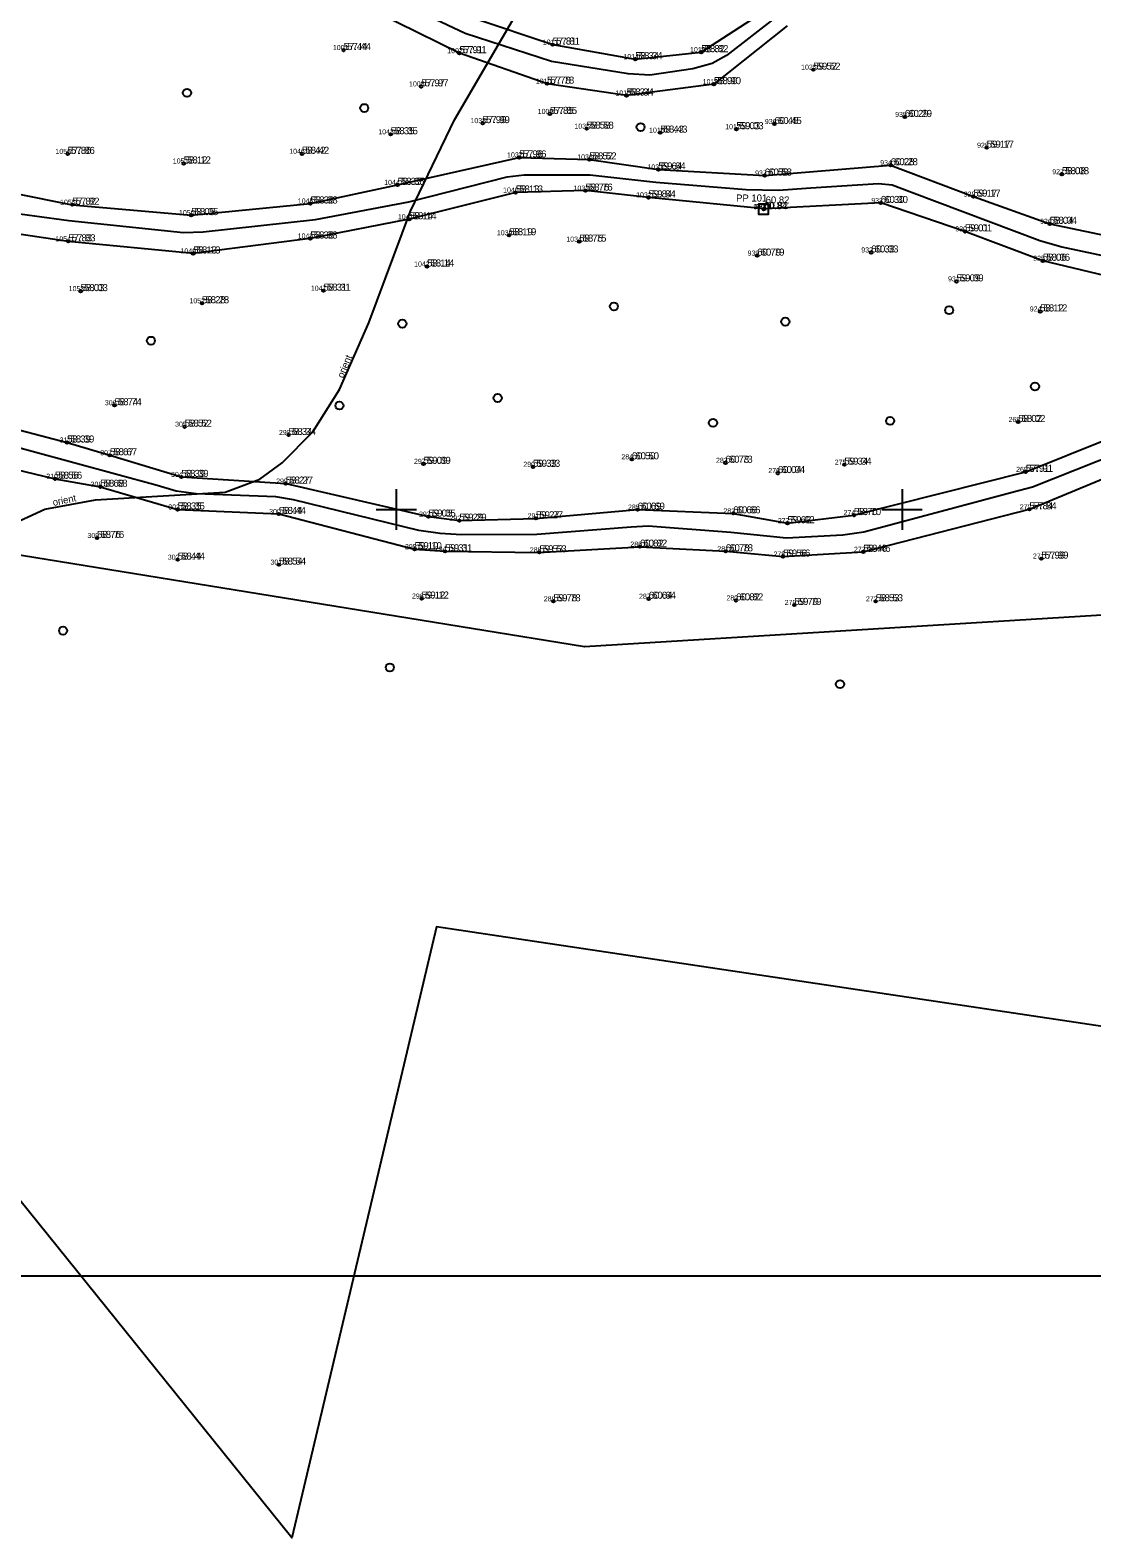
# Model space of a CAD drawing. Extents: x 554846 to 556995, y 6445875 to 6446723.
# Drawn here: x 555263.8 to 555368.8, y 6445948.4 to 6446097.4 of the extents above; entities that cross this region are included whole.
import ezdxf

# ---------------------------------------------------------------- set-up
doc = ezdxf.new("R2010")
doc.units = 0
for name, color, linetype in [('ALUSVORK', 7, 'Continuous'), ('HALJASTUS', 7, 'Continuous'), ('KORGUS-EH2000', 7, 'Continuous'), ('MOOTKORG-EH2000', 7, 'Continuous'), ('MOOTKORGMUU-EH2000', 7, 'Continuous'), ('MOOTMPUNKT', 7, 'Continuous'), ('MOOTNR', 7, 'Continuous'), ('MOOTPIIR', 7, 'Continuous'), ('PIIR', 7, 'Continuous'), ('SITRASS', 7, 'Continuous'), ('TEE', 7, 'Continuous'), ('VORK', 7, 'Continuous'), ('VORMISTUS', 7, 'Continuous')]:
    doc.layers.add(name, color=color, linetype=linetype)

msp = doc.modelspace()

# ---------------------------------------------------------------- linework, layer by layer
at = {"layer": 'ALUSVORK'}
msp.add_lwpolyline([(555336.81, 6446080.17), (555335.81, 6446080.17), (555335.81, 6446079.17), (555336.81, 6446079.17)], close=True, dxfattribs=at)
msp.add_circle((555336.31, 6446079.67), 0.05, dxfattribs=at)
at = {"layer": 'HALJASTUS'}
for centre in [(555279.31, 6446091.18), (555296.83, 6446089.67), (555324.15, 6446087.79), (555321.51, 6446070.07), (555354.66, 6446069.69), (555300.6, 6446068.37), (555338.46, 6446068.56), (555275.74, 6446066.68), (555363.14, 6446062.15), (555310.02, 6446061.02), (555294.38, 6446060.27), (555331.31, 6446058.57), (555348.82, 6446058.76), (555267.06, 6446038.03), (555299.36, 6446034.4), (555343.87, 6446032.75)]:
    msp.add_circle(centre, 0.4, dxfattribs=at)
at = {"layer": 'KORGUS-EH2000'}
for centre in [(555294.8, 6446095.4), (555315.46, 6446095.94), (555330.14, 6446095.19), (555306.24, 6446095.09), (555323.63, 6446094.5), (555341.22, 6446093.46), (555302.46, 6446091.81), (555314.9, 6446092.08), (555322.76, 6446090.91), (555331.39, 6446092.03), (555308.53, 6446088.18), (555315.18, 6446089.09), (555337.39, 6446088.09), (555350.27, 6446088.79), (555299.44, 6446087.08), (555318.81, 6446087.63), (555326.09, 6446087.24), (555333.62, 6446087.58), (555267.5, 6446085.14), (555290.67, 6446085.15), (555312.15, 6446084.79), (555358.37, 6446085.75), (555278.98, 6446084.19), (555319.08, 6446084.59), (555325.91, 6446083.6), (555348.87, 6446084.02), (555300.12, 6446082.08), (555336.42, 6446083), (555365.8, 6446083.13), (555291.51, 6446080.24), (555311.81, 6446081.32), (555318.7, 6446081.51), (555324.93, 6446080.84), (555347.89, 6446080.29), (555357.05, 6446080.92), (555267.96, 6446080.12), (555279.72, 6446079.09), (555301.28, 6446078.68), (555356.22, 6446077.48), (555364.6, 6446078.23), (555267.57, 6446076.5), (555291.5, 6446076.78), (555311.15, 6446077.1), (555318.08, 6446076.47), (555279.92, 6446075.3), (555335.68, 6446075.09), (555346.95, 6446075.4), (555363.92, 6446074.58), (555303.04, 6446074.01), (555268.79, 6446071.58), (555292.8, 6446071.62), (555355.38, 6446072.54), (555280.78, 6446070.38), (555363.65, 6446069.57), (555272.14, 6446060.3), (555279.08, 6446058.18), (555361.48, 6446058.65), (555267.45, 6446056.62), (555289.35, 6446057.36), (555271.68, 6446055.36), (555323.28, 6446054.96), (555302.69, 6446054.51), (555313.51, 6446054.22), (555332.54, 6446054.62), (555337.72, 6446053.6), (555344.3, 6446054.43), (555362.23, 6446053.72), (555266.25, 6446053.04), (555270.73, 6446052.25), (555278.75, 6446053.22), (555289.07, 6446052.56), (555278.38, 6446050), (555288.38, 6446049.56), (555303.18, 6446049.3), (555313.8, 6446049.13), (555323.86, 6446049.99), (555333.31, 6446049.62), (555345.24, 6446049.45), (555362.59, 6446050.02), (555306.24, 6446048.9), (555338.67, 6446048.65), (555270.41, 6446047.19), (555301.81, 6446046.08), (555324.09, 6446046.33), (555278.39, 6446045.04), (555288.39, 6446044.55), (555304.82, 6446045.87), (555314.15, 6446045.77), (555332.57, 6446045.87), (555338.24, 6446045.35), (555346.17, 6446045.82), (555363.77, 6446045.15), (555302.5, 6446041.2), (555315.53, 6446040.93), (555324.95, 6446041.18), (555333.59, 6446041.02), (555339.35, 6446040.57), (555347.4, 6446040.93)]:
    msp.add_circle(centre, 0.125, dxfattribs=at)
at = {"layer": 'MOOTMPUNKT'}
for centre in [(555294.8, 6446095.4), (555315.46, 6446095.94), (555330.14, 6446095.19), (555306.24, 6446095.09), (555323.63, 6446094.5), (555341.22, 6446093.46), (555302.46, 6446091.81), (555314.9, 6446092.08), (555322.76, 6446090.91), (555331.39, 6446092.03), (555308.53, 6446088.18), (555315.18, 6446089.09), (555337.39, 6446088.09), (555350.27, 6446088.79), (555299.44, 6446087.08), (555318.81, 6446087.63), (555326.09, 6446087.24), (555333.62, 6446087.58), (555267.5, 6446085.14), (555290.67, 6446085.15), (555312.15, 6446084.79), (555358.37, 6446085.75), (555278.98, 6446084.19), (555319.08, 6446084.59), (555325.91, 6446083.6), (555348.87, 6446084.02), (555300.12, 6446082.08), (555336.42, 6446083), (555365.8, 6446083.13), (555291.51, 6446080.24), (555311.81, 6446081.32), (555318.7, 6446081.51), (555324.93, 6446080.84), (555347.89, 6446080.29), (555357.05, 6446080.92), (555267.96, 6446080.12), (555279.72, 6446079.09), (555336.31, 6446079.67), (555336.39, 6446079.7), (555301.28, 6446078.68), (555356.22, 6446077.48), (555364.6, 6446078.23), (555267.57, 6446076.5), (555291.5, 6446076.78), (555311.15, 6446077.1), (555318.08, 6446076.47), (555279.92, 6446075.3), (555335.68, 6446075.09), (555346.95, 6446075.4), (555363.92, 6446074.58), (555303.04, 6446074.01), (555268.79, 6446071.58), (555292.8, 6446071.62), (555355.38, 6446072.54), (555280.78, 6446070.38), (555363.65, 6446069.57), (555272.14, 6446060.3), (555279.08, 6446058.18), (555361.48, 6446058.65), (555267.45, 6446056.62), (555289.35, 6446057.36), (555271.68, 6446055.36), (555323.28, 6446054.96), (555302.69, 6446054.51), (555313.51, 6446054.22), (555332.54, 6446054.62), (555337.72, 6446053.6), (555344.3, 6446054.43), (555362.23, 6446053.72), (555266.25, 6446053.04), (555270.73, 6446052.25), (555278.75, 6446053.22), (555289.07, 6446052.56), (555278.38, 6446050), (555288.38, 6446049.56), (555303.18, 6446049.3), (555313.8, 6446049.13), (555323.86, 6446049.99), (555333.31, 6446049.62), (555345.24, 6446049.45), (555362.59, 6446050.02), (555306.24, 6446048.9), (555338.67, 6446048.65), (555270.41, 6446047.19), (555301.81, 6446046.08), (555324.09, 6446046.33), (555278.39, 6446045.04), (555288.39, 6446044.55), (555304.82, 6446045.87), (555314.15, 6446045.77), (555332.57, 6446045.87), (555338.24, 6446045.35), (555346.17, 6446045.82), (555363.77, 6446045.15), (555302.5, 6446041.2), (555315.53, 6446040.93), (555324.95, 6446041.18), (555333.59, 6446041.02), (555339.35, 6446040.57), (555347.4, 6446040.93)]:
    msp.add_circle(centre, 0.125, dxfattribs=at)
at = {"layer": 'MOOTPIIR'}
msp.add_lwpolyline([(555856.56, 6446356.05), (555752.84, 6446263.06), (555653.54, 6446239.26), (555594.53, 6446196.06), (555554.98, 6446185.17), (555476.19, 6446171.98), (555473.22, 6446121.18), (555464.98, 6446086.88), (555439.93, 6446060.82), (555399.38, 6446041.36), (555318.62, 6446036.42), (555233.24, 6446050.27)], dxfattribs=at)
at = {"layer": 'PIIR'}
msp.add_lwpolyline([(555848.15, 6446270.05), (555770.44, 6446257.1), (555601.76, 6446236.19), (555592.08, 6446205.8), (555590.17, 6446199.81), (555547.72, 6446198.88), (555471.93, 6446166.68), (555437.75, 6445988.89), (555430.84, 6445989.84), (555424.9, 6445990.66), (555394.94, 6445995.15), (555348.46, 6446002.11), (555303.97, 6446008.78), (555290.27, 6445950.91), (555289.66, 6445948.39), (555259.76, 6445985.47)], dxfattribs=at)
at = {"layer": 'SITRASS'}
msp.add_lwpolyline([(555261.53, 6446048.32), (555265.26, 6446050.03), (555270.26, 6446050.97), (555283.07, 6446051.71), (555286.51, 6446053), (555288.72, 6446054.6), (555291.74, 6446057.68), (555294.38, 6446061.86), (555297.27, 6446068.45), (555301.4, 6446079.47), (555305.76, 6446088.51), (555311.73, 6446098.73)], dxfattribs=at)
at = {"layer": 'TEE'}
for points in [[(555256.61, 6446082.39), (555267.96, 6446080.12), (555279.72, 6446079.09), (555291.51, 6446080.24), (555300.12, 6446082.08), (555312.15, 6446084.79), (555319.08, 6446084.59), (555325.91, 6446083.6), (555336.42, 6446083), (555348.87, 6446084.02), (555357.05, 6446080.92), (555364.6, 6446078.23), (555374.38, 6446076.19), (555383.78, 6446075.37), (555390.8, 6446076.13), (555396.02, 6446079.96), (555405.42, 6446089.57), (555411.89, 6446096.58), (555419.56, 6446103.46)], [(555419.45, 6446099.97), (555414.31, 6446095.01), (555407.49, 6446086.81), (555398.56, 6446078), (555391.3, 6446072.86), (555383.86, 6446071.46), (555373.85, 6446072.2), (555363.92, 6446074.58), (555356.22, 6446077.48), (555347.89, 6446080.29), (555336.39, 6446079.7), (555324.93, 6446080.84), (555318.7, 6446081.51), (555311.81, 6446081.32), (555301.28, 6446078.68), (555291.5, 6446076.78), (555279.92, 6446075.3), (555267.57, 6446076.5), (555255.14, 6446078.33)], [(555337.65, 6446098.75), (555332.63, 6446094.86), (555331.22, 6446094.06), (555329.3, 6446093.54), (555325.06, 6446092.92), (555322.93, 6446093.04), (555315.35, 6446094.28), (555306.81, 6446097.03), (555299.18, 6446100.65)], [(555338.65, 6446097.8), (555331.39, 6446092.03), (555322.76, 6446090.91), (555314.9, 6446092.08), (555306.24, 6446095.09), (555298.02, 6446099.16)], [(555307.6, 6446098.59), (555315.46, 6446095.94), (555323.63, 6446094.5), (555330.14, 6446095.19), (555336.09, 6446099.06)], [(555260.14, 6446058.52), (555267.45, 6446056.62), (555271.68, 6446055.36), (555278.75, 6446053.22), (555289.07, 6446052.56), (555303.18, 6446049.3), (555306.24, 6446048.9), (555313.8, 6446049.13), (555323.86, 6446049.99), (555333.31, 6446049.62), (555338.67, 6446048.65), (555345.24, 6446049.45), (555362.23, 6446053.72), (555370.46, 6446057.03), (555379.96, 6446060.43), (555389.86, 6446059.75), (555402.8, 6446059.54), (555410.15, 6446060.85), (555416.44, 6446065.08), (555425.62, 6446070.28), (555431.48, 6446073.77), (555442.06, 6446083.57), (555449.19, 6446092.47), (555452.21, 6446097.57)], [(555260.83, 6446079.49), (555267.63, 6446078.55), (555278.96, 6446077.39), (555280.91, 6446077.45), (555292.02, 6446078.67), (555301.24, 6446080.41), (555310.97, 6446082.87), (555312.63, 6446083.06), (555315.59, 6446083.06), (555319.13, 6446083.06), (555325.66, 6446082.35), (555334.6, 6446081.62), (555337.8, 6446081.56), (555340.99, 6446081.78), (555345.59, 6446082.09), (555347.68, 6446082.23), (555349.03, 6446082.09), (555350.95, 6446081.36), (555363.63, 6446076.59), (555365.8, 6446075.96), (555374.01, 6446074.2)], [(555371.37, 6446055.57), (555362.89, 6446052.22), (555360.89, 6446051.68), (555346.21, 6446047.75), (555344.13, 6446047.47), (555338.59, 6446047.16), (555333.07, 6446047.72), (555324.91, 6446048.34), (555323.23, 6446048.27), (555313.89, 6446047.54), (555306.46, 6446047.5), (555304.33, 6446047.64), (555302.22, 6446047.92), (555289.82, 6446050.95), (555288.08, 6446051.24), (555280.21, 6446051.55), (555278.25, 6446051.8), (555276.36, 6446052.39), (555259.85, 6446056.85)], [(555259.12, 6446054.74), (555266.25, 6446053.04), (555270.73, 6446052.25), (555278.38, 6446050), (555288.38, 6446049.56), (555301.81, 6446046.08), (555304.82, 6446045.87), (555314.03, 6446045.77), (555324.09, 6446046.33), (555332.57, 6446045.87), (555338.24, 6446045.35), (555346.17, 6446045.82), (555362.59, 6446050.02), (555371.83, 6446053.87)]]:
    msp.add_lwpolyline(points, dxfattribs=at)
at = {"layer": 'VORK'}
for p, q in [((555300, 6446052), (555300, 6446048)), ((555350, 6446052), (555350, 6446048)), ((555298, 6446050), (555302, 6446050)), ((555348, 6446050), (555352, 6446050))]:
    msp.add_line(p, q, dxfattribs=at)
at = {"layer": 'VORMISTUS'}
msp.add_lwpolyline([(555573.73, 6445974.27), (555573.73, 6446387.77), (554994.23, 6446387.77), (554994.23, 6445974.27), (555573.73, 6445974.27)], dxfattribs=at)

# ---------------------------------------------------------------- texts
at = {"layer": 'ALUSVORK'}
for s, p in [('PP 101', (555333.6, 6446080.43)), ('60.82', (555336.52, 6446080.24))]:
    msp.add_text(s, height=0.7, dxfattribs=at).set_placement(p)
at = {"layer": 'KORGUS-EH2000'}
for s, p in [('57.44', (555295.15, 6446095.4)), ('57.91', (555306.59, 6446095.09)), ('57.81', (555315.81, 6446095.94)), ('58.82', (555330.49, 6446095.19)), ('58.34', (555323.98, 6446094.5)), ('59.52', (555341.57, 6446093.46)), ('57.97', (555302.81, 6446091.81)), ('57.78', (555315.25, 6446092.08)), ('58.90', (555331.74, 6446092.03)), ('58.34', (555323.11, 6446090.91)), ('57.85', (555315.53, 6446089.09)), ('60.29', (555350.62, 6446088.79)), ('57.99', (555308.88, 6446088.18)), ('58.58', (555319.16, 6446087.63)), ('58.43', (555326.44, 6446087.24)), ('59.03', (555333.97, 6446087.58)), ('60.45', (555337.74, 6446088.09)), ('58.35', (555299.79, 6446087.08)), ('59.17', (555358.72, 6446085.75)), ('57.86', (555267.85, 6446085.14)), ('58.12', (555279.33, 6446084.19)), ('58.42', (555291.02, 6446085.15)), ('57.96', (555312.5, 6446084.79)), ('58.52', (555319.43, 6446084.59)), ('59.64', (555326.26, 6446083.6)), ('60.58', (555336.77, 6446083)), ('60.28', (555349.22, 6446084.02)), ('58.08', (555366.15, 6446083.13)), ('58.35', (555300.47, 6446082.08)), ('58.13', (555312.16, 6446081.32)), ('58.76', (555319.05, 6446081.51)), ('57.82', (555268.31, 6446080.12)), ('58.38', (555291.86, 6446080.24)), ('59.84', (555325.28, 6446080.84)), ('60.30', (555348.24, 6446080.29)), ('59.17', (555357.4, 6446080.92)), ('58.05', (555280.07, 6446079.09)), ('58.14', (555301.63, 6446078.68)), ('58.04', (555364.95, 6446078.23)), ('58.38', (555291.85, 6446076.78)), ('58.19', (555311.5, 6446077.1)), ('59.01', (555356.57, 6446077.48)), ('57.83', (555267.92, 6446076.5)), ('58.13', (555280.27, 6446075.3)), ('58.75', (555318.43, 6446076.47)), ('60.33', (555347.3, 6446075.4)), ('58.14', (555303.39, 6446074.01)), ('60.79', (555336.03, 6446075.09)), ('58.06', (555364.27, 6446074.58)), ('59.09', (555355.72, 6446072.54)), ('58.03', (555269.14, 6446071.58)), ('58.31', (555293.15, 6446071.62)), ('58.28', (555281.13, 6446070.38)), ('58.12', (555364, 6446069.57)), ('58.74', (555272.49, 6446060.3)), ('58.52', (555279.43, 6446058.18)), ('58.34', (555289.7, 6446057.36)), ('58.02', (555361.83, 6446058.65)), ('58.39', (555267.8, 6446056.62)), ('58.67', (555272.03, 6446055.36)), ('59.09', (555303.04, 6446054.51)), ('60.50', (555323.63, 6446054.96)), ('60.73', (555332.89, 6446054.62)), ('59.34', (555344.65, 6446054.43)), ('58.56', (555266.6, 6446053.04)), ('58.39', (555279.1, 6446053.22)), ('59.33', (555313.86, 6446054.22)), ('60.04', (555338.07, 6446053.6)), ('57.91', (555362.58, 6446053.72)), ('58.68', (555271.08, 6446052.25)), ('58.27', (555289.42, 6446052.56)), ('58.35', (555278.73, 6446050)), ('60.69', (555324.21, 6446049.99)), ('57.84', (555362.94, 6446050.02)), ('58.44', (555288.73, 6446049.56)), ('59.05', (555303.53, 6446049.3)), ('59.29', (555306.59, 6446048.9)), ('59.27', (555314.15, 6446049.13)), ('60.66', (555333.66, 6446049.62)), ('59.62', (555339.02, 6446048.65)), ('58.70', (555345.59, 6446049.45)), ('58.76', (555270.76, 6446047.19)), ('59.10', (555302.16, 6446046.08)), ('59.31', (555305.17, 6446045.87)), ('59.53', (555314.5, 6446045.77)), ('60.82', (555324.44, 6446046.33)), ('60.78', (555332.92, 6446045.87)), ('58.46', (555346.52, 6446045.82)), ('58.44', (555278.74, 6446045.04)), ('58.54', (555288.74, 6446044.55)), ('59.56', (555338.59, 6446045.35)), ('57.99', (555364.11, 6446045.15)), ('59.12', (555302.85, 6446041.2)), ('59.78', (555315.88, 6446040.93)), ('60.64', (555325.3, 6446041.18)), ('60.82', (555333.94, 6446041.02)), ('58.53', (555347.75, 6446040.93)), ('59.79', (555339.7, 6446040.57))]:
    msp.add_text(s, height=0.7, dxfattribs=at).set_placement(p)
at = {"layer": 'MOOTKORG-EH2000'}
for s, p in [('57.44', (555294.8, 6446095.4)), ('57.91', (555306.24, 6446095.09)), ('57.81', (555315.46, 6446095.94)), ('58.82', (555330.14, 6446095.19)), ('58.34', (555323.63, 6446094.5)), ('59.52', (555341.22, 6446093.46)), ('57.97', (555302.46, 6446091.81)), ('57.78', (555314.9, 6446092.08)), ('58.90', (555331.39, 6446092.03)), ('58.34', (555322.76, 6446090.91)), ('57.85', (555315.18, 6446089.09)), ('60.29', (555350.27, 6446088.79)), ('57.99', (555308.53, 6446088.18)), ('58.58', (555318.81, 6446087.63)), ('58.43', (555326.09, 6446087.24)), ('59.03', (555333.62, 6446087.58)), ('60.45', (555337.39, 6446088.09)), ('58.35', (555299.44, 6446087.08)), ('59.17', (555358.37, 6446085.75)), ('57.86', (555267.5, 6446085.14)), ('58.12', (555278.98, 6446084.19)), ('58.42', (555290.67, 6446085.15)), ('57.96', (555312.15, 6446084.79)), ('58.52', (555319.08, 6446084.59)), ('59.64', (555325.91, 6446083.6)), ('60.58', (555336.42, 6446083)), ('60.28', (555348.87, 6446084.02)), ('58.08', (555365.8, 6446083.13)), ('58.35', (555300.12, 6446082.08)), ('58.13', (555311.81, 6446081.32)), ('58.76', (555318.7, 6446081.51)), ('57.82', (555267.96, 6446080.12)), ('58.38', (555291.51, 6446080.24)), ('59.84', (555324.93, 6446080.84)), ('60.82', (555336.39, 6446079.7)), ('60.30', (555347.89, 6446080.29)), ('59.17', (555357.05, 6446080.92)), ('58.05', (555279.72, 6446079.09)), ('58.14', (555301.28, 6446078.68)), ('58.04', (555364.6, 6446078.23)), ('58.38', (555291.5, 6446076.78)), ('58.19', (555311.15, 6446077.1)), ('59.01', (555356.22, 6446077.48)), ('57.83', (555267.57, 6446076.5)), ('58.13', (555279.92, 6446075.3)), ('58.75', (555318.08, 6446076.47)), ('60.33', (555346.95, 6446075.4)), ('58.14', (555303.04, 6446074.01)), ('60.79', (555335.68, 6446075.09)), ('58.06', (555363.92, 6446074.58)), ('59.09', (555355.38, 6446072.54)), ('58.03', (555268.79, 6446071.58)), ('58.31', (555292.8, 6446071.62)), ('58.28', (555280.78, 6446070.38)), ('58.12', (555363.65, 6446069.57)), ('58.74', (555272.14, 6446060.3)), ('58.52', (555279.08, 6446058.18)), ('58.34', (555289.35, 6446057.36)), ('58.02', (555361.48, 6446058.65)), ('58.39', (555267.45, 6446056.62)), ('58.67', (555271.68, 6446055.36)), ('59.09', (555302.69, 6446054.51)), ('60.50', (555323.28, 6446054.96)), ('60.73', (555332.54, 6446054.62)), ('59.34', (555344.3, 6446054.43)), ('58.56', (555266.25, 6446053.04)), ('58.39', (555278.75, 6446053.22)), ('59.33', (555313.51, 6446054.22)), ('60.04', (555337.72, 6446053.6)), ('57.91', (555362.23, 6446053.72)), ('58.68', (555270.73, 6446052.25)), ('58.27', (555289.07, 6446052.56)), ('58.35', (555278.38, 6446050)), ('60.69', (555323.86, 6446049.99)), ('57.84', (555362.59, 6446050.02)), ('58.44', (555288.38, 6446049.56)), ('59.05', (555303.18, 6446049.3)), ('59.29', (555306.24, 6446048.9)), ('59.27', (555313.8, 6446049.13)), ('60.66', (555333.31, 6446049.62)), ('59.62', (555338.67, 6446048.65)), ('58.70', (555345.24, 6446049.45)), ('58.76', (555270.41, 6446047.19)), ('59.10', (555301.81, 6446046.08)), ('59.31', (555304.82, 6446045.87)), ('59.53', (555314.15, 6446045.77)), ('60.82', (555324.09, 6446046.33)), ('60.78', (555332.57, 6446045.87)), ('58.46', (555346.17, 6446045.82)), ('58.44', (555278.39, 6446045.04)), ('58.54', (555288.39, 6446044.55)), ('59.56', (555338.24, 6446045.35)), ('57.99', (555363.77, 6446045.15)), ('59.12', (555302.5, 6446041.2)), ('59.78', (555315.53, 6446040.93)), ('60.64', (555324.95, 6446041.18)), ('60.82', (555333.59, 6446041.02)), ('58.53', (555347.4, 6446040.93)), ('59.79', (555339.35, 6446040.57))]:
    msp.add_text(s, height=0.7, dxfattribs=at).set_placement(p)
at = {"layer": 'MOOTKORGMUU-EH2000'}
msp.add_text('60.84', height=0.7, dxfattribs=at).set_placement((555336.31, 6446079.67))
at = {"layer": 'MOOTNR'}
for s, p in [('1001', (555293.73, 6446095.4)), ('1007', (555305.04, 6446095.09)), ('1011', (555314.48, 6446095.94)), ('1019', (555329.04, 6446095.19)), ('1014', (555322.45, 6446094.5)), ('1025', (555340.02, 6446093.46)), ('1008', (555301.26, 6446091.81)), ('1010', (555313.8, 6446092.08)), ('1018', (555330.29, 6446092.03)), ('1015', (555321.66, 6446090.91)), ('1009', (555313.98, 6446089.09)), ('935', (555349.32, 6446088.79)), ('1038', (555307.33, 6446088.18)), ('1035', (555317.61, 6446087.63)), ('1017', (555332.52, 6446087.58)), ('936', (555336.44, 6446088.09)), ('1043', (555298.22, 6446087.08)), ('1016', (555324.99, 6446087.24)), ('1056', (555266.3, 6446085.14)), ('1046', (555289.42, 6446085.15)), ('1037', (555310.95, 6446084.79)), ('1036', (555317.89, 6446084.59)), ('928', (555357.42, 6446085.75)), ('1051', (555277.9, 6446084.19)), ('1031', (555324.84, 6446083.6)), ('937', (555335.47, 6446083)), ('934', (555347.84, 6446084.02)), ('927', (555364.85, 6446083.13)), ('1044', (555298.8, 6446082.08)), ('1033', (555317.53, 6446081.51)), ('1055', (555266.76, 6446080.12)), ('1045', (555290.26, 6446080.24)), ('1040', (555310.56, 6446081.32)), ('1032', (555323.71, 6446080.84)), ('933', (555346.96, 6446080.29)), ('929', (555356.1, 6446080.92)), ('1050', (555278.52, 6446079.09)), ('1041', (555300.16, 6446078.68)), ('940', (555335.31, 6446079.67)), ('938', (555335.44, 6446079.7)), ('1039', (555309.95, 6446077.1)), ('930', (555355.27, 6446077.48)), ('926', (555363.65, 6446078.23)), ('1054', (555266.3, 6446076.5)), ('1048', (555290.25, 6446076.78)), ('1034', (555316.81, 6446076.47)), ('932', (555345.97, 6446075.4)), ('1049', (555278.67, 6446075.3)), ('1042', (555301.76, 6446074.01)), ('939', (555334.73, 6446075.09)), ('925', (555362.97, 6446074.58)), ('931', (555354.55, 6446072.54)), ('1053', (555267.61, 6446071.58)), ('1047', (555291.55, 6446071.62)), ('1052', (555279.55, 6446070.38)), ('924', (555362.63, 6446069.57)), ('306', (555271.19, 6446060.3)), ('305', (555278.13, 6446058.18)), ('268', (555360.53, 6446058.65)), ('311', (555266.72, 6446056.62)), ('298', (555288.4, 6446057.36)), ('307', (555270.73, 6446055.36)), ('297', (555301.75, 6446054.51)), ('284', (555322.25, 6446054.96)), ('283', (555331.61, 6446054.62)), ('310', (555265.4, 6446053.04)), ('304', (555277.73, 6446053.22)), ('290', (555312.56, 6446054.22)), ('276', (555336.78, 6446053.6)), ('275', (555343.35, 6446054.43)), ('269', (555361.28, 6446053.72)), ('308', (555269.78, 6446052.25)), ('299', (555288.12, 6446052.56)), ('303', (555277.46, 6446050)), ('300', (555287.43, 6446049.56)), ('293', (555302.25, 6446049.3)), ('292', (555305.26, 6446048.9)), ('291', (555312.98, 6446049.13)), ('285', (555322.91, 6446049.99)), ('282', (555332.34, 6446049.62)), ('277', (555337.72, 6446048.65)), ('274', (555344.22, 6446049.45)), ('270', (555361.64, 6446050.02)), ('309', (555269.46, 6446047.19)), ('295', (555300.86, 6446046.08)), ('294', (555303.8, 6446045.87)), ('288', (555313.2, 6446045.77)), ('286', (555323.14, 6446046.33)), ('281', (555331.74, 6446045.87)), ('273', (555345.25, 6446045.82)), ('302', (555277.41, 6446045.04)), ('301', (555287.56, 6446044.55)), ('278', (555337.29, 6446045.35)), ('271', (555362.94, 6446045.15)), ('296', (555301.55, 6446041.2)), ('287', (555324, 6446041.18)), ('289', (555314.58, 6446040.93)), ('280', (555332.64, 6446041.02)), ('279', (555338.4, 6446040.57)), ('272', (555346.43, 6446040.93))]:
    msp.add_text(s, height=0.5, dxfattribs=at).set_placement(p)
at = {"layer": 'SITRASS'}
for rotation, p in [(67.4666, (555294.76, 6446062.93)), (11.5383, (555266.1, 6446050.35))]:
    msp.add_text('orient', height=0.7, rotation=rotation, dxfattribs=at).set_placement(p)

doc.saveas('drawing.dxf')
